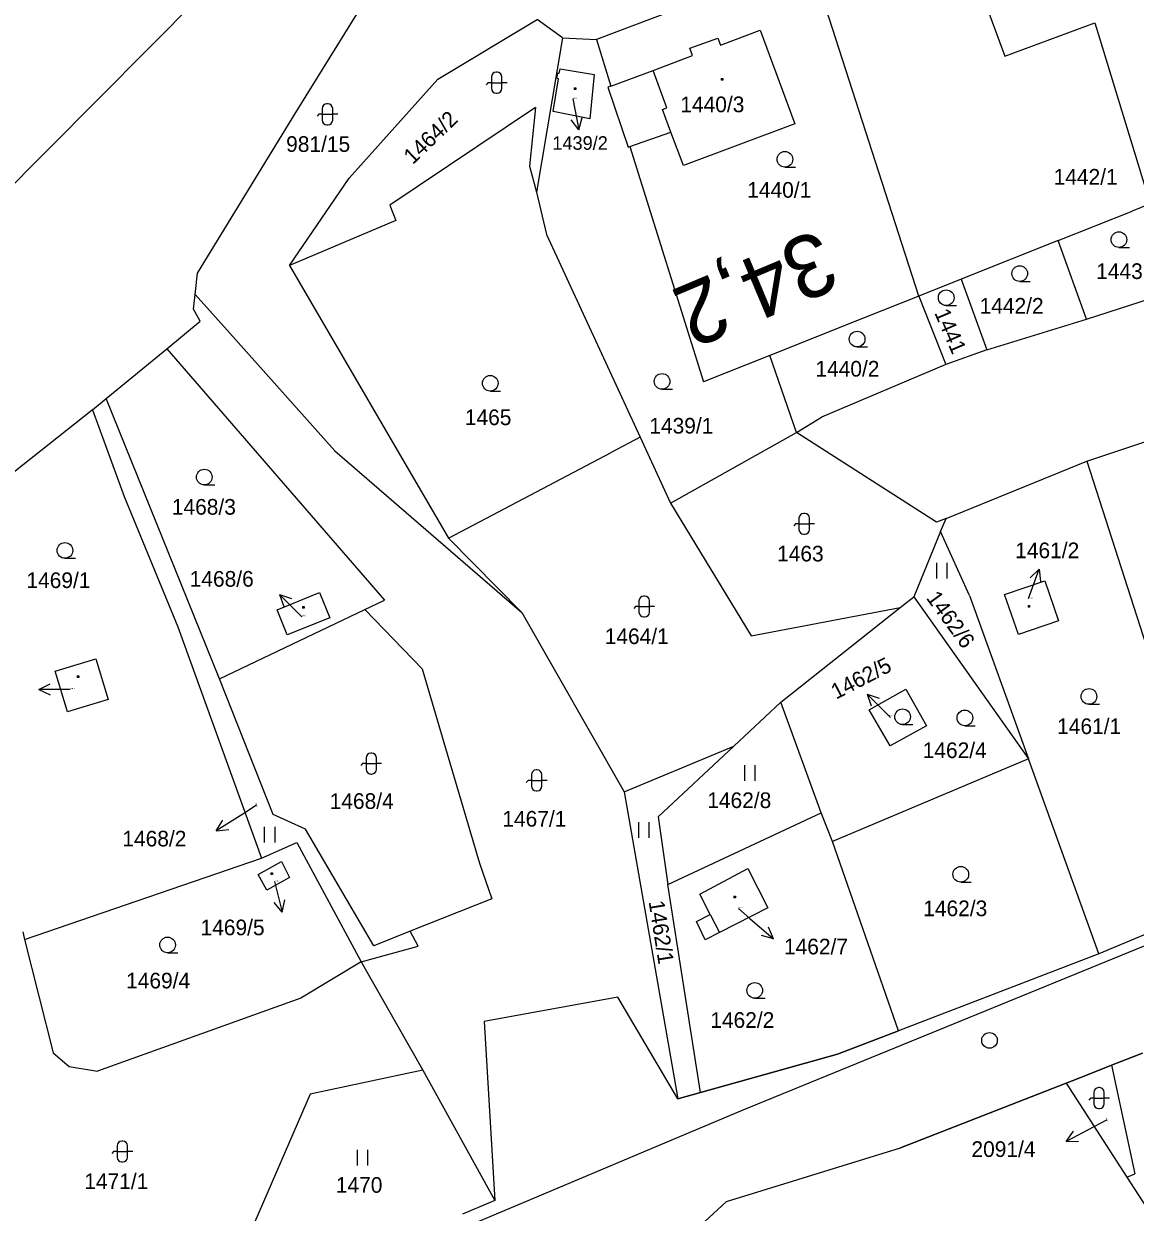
# Model space of a CAD drawing. Extents: x -805730 to -804640, y -1150889 to -1150366.
# Drawn here: x -805108.7 to -805002.2, y -1150618.3 to -1150504.4 of the extents above; entities that cross this region are included whole.
import ezdxf

# ---------------------------------------------------------------- set-up
doc = ezdxf.new("R2010")
doc.units = 0
for name, color, linetype in [('Default', 7, 'Continuous'), ('kilometráž - vrstava 7', 7, 'Continuous'), ('kn_celek - Cisla parcel pomocna', 7, 'Continuous'), ('kn_celek - Cisla pozemkovych parcel', 7, 'Continuous'), ('kn_celek - Cisla stavebnich parcel', 7, 'Continuous'), ('kn_celek - Hranice parcel', 7, 'Continuous'), ('kn_celek - Vnitrni kresby', 7, 'Continuous'), ('kn_celek - Znacky budov', 7, 'Continuous'), ('kn_celek - Znacky kultur', 7, 'Continuous'), ('plochy - SZDC', 7, 'Continuous'), ('PSR_C2_2_trasa_Vimperk - Kabelová trasa', 7, 'Continuous')]:
    doc.layers.add(name, color=color, linetype=linetype)

# ---------------------------------------------------------------- blocks, each defined once
blk = doc.blocks.new('316')
at = {"layer": 'Default'}
for p, q in [((-5, 15.5), (-5, 4.5)), ((0.5, 20), (-0.5, 20)), ((5, 4.5), (5, 15.5)), ((-8.3, 10), (-10, 8.1)), ((-5, 10), (-8.3, 10)), ((-5, 10), (5, 10)), ((-0.5, 0), (0.5, 0)), ((10, 10), (5, 10))]:
    blk.add_line(p, q, dxfattribs=at)
for centre, start, end in [((-0.5, 15.5), 90, 180), ((0.5, 15.5), 0, 90), ((-0.5, 4.5), 180, 270), ((0.5, 4.5), 270, 0)]:
    blk.add_arc(centre, 4.5, start, end, dxfattribs=at)
blk = doc.blocks.new('304')
at = {"layer": 'Default'}
blk.add_line((-0.1, 0), (9.9, 0), dxfattribs=at)
blk.add_circle((-0.1, 7.5), 7.5, dxfattribs=at)
blk = doc.blocks.new('306')
at = {"layer": 'Default'}
for p, q in [((-5.2, 0), (-5.2, 15)), ((4.8, 0), (4.8, 15))]:
    blk.add_line(p, q, dxfattribs=at)
blk = doc.blocks.new('402')
at = {"layer": 'Default'}
for p, q in [((-0.8, 0.8), (0.7, 0.8)), ((-0.8, 0.8), (-0.8, -0.7)), ((0.7, 0.8), (0.7, -0.7)), ((0.7, -0.7), (-0.8, -0.7))]:
    blk.add_line(p, q, dxfattribs=at)
blk = doc.blocks.new('Z61')
at = {"layer": 'Default'}
for p, q in [((0, 0), (30, 0)), ((30, 0), (19.2, 5.3)), ((30, 0), (19.2, -5.3))]:
    blk.add_line(p, q, dxfattribs=at)

msp = doc.modelspace()

# ---------------------------------------------------------------- linework, layer by layer
at = {"layer": 'kilometráž - vrstava 7'}
msp.add_circle((-805016.2, -1150601.85), 0.75, dxfattribs=at)
at = {"layer": 'kn_celek - Cisla parcel pomocna'}
for p, q in [((-805025.69, -1150570.9), (-805025.8, -1150570.79)), ((-805086.41, -1150579.31), (-805087.74, -1150580.16)), ((-805040.25, -1150589.23), (-805039.17, -1150590.16)), ((-805004.99, -1150609.51), (-805006.2, -1150610.14))]:
    msp.add_line(p, q, dxfattribs=at)
at = {"layer": 'kn_celek - Hranice parcel'}
for p, q in [((-805079.5, -1150489.41), (-805112.27, -1150522.42)), ((-805018.53, -1150497.21), (-805014.72, -1150507.54)), ((-805033.4, -1150498.22), (-805053.85, -1150505.95)), ((-805022.97, -1150530.54), (-805033.4, -1150498.22)), ((-805082.65, -1150512.94), (-805074.55, -1150499.86)), ((-805069.04, -1150509.76), (-805059.52, -1150504.03)), ((-805057.1, -1150505.8), (-805059.52, -1150504.03)), ((-805014.72, -1150507.54), (-805006.12, -1150504.36)), ((-805006.12, -1150504.36), (-805000.8, -1150521.71)), ((-805041.98, -1150506.5), (-805038.18, -1150505.06)), ((-805038.18, -1150505.06), (-805034.85, -1150514.03)), ((-805057.1, -1150505.8), (-805059.6, -1150520.58)), ((-805057.1, -1150505.8), (-805053.85, -1150505.95)), ((-805053.85, -1150505.95), (-805052.46, -1150510.42)), ((-805044.9, -1150506.79), (-805042.23, -1150505.81)), ((-805044.64, -1150507.48), (-805044.9, -1150506.79)), ((-805042.23, -1150505.81), (-805041.98, -1150506.5)), ((-805048.42, -1150508.92), (-805044.64, -1150507.48)), ((-805057.41, -1150509.19), (-805057.33, -1150508.76)), ((-805057.33, -1150508.76), (-805054.07, -1150509.3)), ((-805052.46, -1150510.42), (-805048.42, -1150508.92)), ((-805077.55, -1150519.25), (-805069.04, -1150509.76)), ((-805058, -1150512.84), (-805057.49, -1150509.72)), ((-805057.63, -1150509.69), (-805057.57, -1150509.17)), ((-805057.49, -1150509.72), (-805057.63, -1150509.69)), ((-805057.57, -1150509.17), (-805057.41, -1150509.19)), ((-805054.07, -1150509.3), (-805054.49, -1150513.55)), ((-805052.46, -1150510.42), (-805052.77, -1150510.53)), ((-805052.77, -1150510.53), (-805050.82, -1150516.26)), ((-805059.7, -1150512.48), (-805073.66, -1150521.82)), ((-805059.7, -1150512.48), (-805060.27, -1150518.1)), ((-805092.06, -1150528.34), (-805082.65, -1150512.94)), ((-805054.49, -1150513.55), (-805058, -1150512.84)), ((-805050.65, -1150516.2), (-805046.73, -1150514.83)), ((-805045.5, -1150518.02), (-805046.73, -1150514.83)), ((-805034.85, -1150514.03), (-805045.5, -1150518.02)), ((-805050.82, -1150516.26), (-805050.65, -1150516.2)), ((-805050.65, -1150516.2), (-805043.6, -1150538.76)), ((-805060.27, -1150518.1), (-805059.6, -1150520.58)), ((-805083.26, -1150527.62), (-805077.55, -1150519.25)), ((-805059.6, -1150520.58), (-805058.64, -1150524.62)), ((-805073.66, -1150521.82), (-805073.06, -1150523.3)), ((-805009.62, -1150525.22), (-805002.53, -1150522.4)), ((-805000.8, -1150521.71), (-805002.53, -1150522.4)), ((-805073.06, -1150523.3), (-805083.26, -1150527.62)), ((-805058.64, -1150524.62), (-805049.67, -1150544.06)), ((-805009.62, -1150525.22), (-805018.9, -1150528.92)), ((-805006.9, -1150532.75), (-805009.62, -1150525.22)), ((-805092.29, -1150530.39), (-805092.06, -1150528.34)), ((-805083.26, -1150527.62), (-805068.03, -1150553.72)), ((-805018.9, -1150528.92), (-805022.97, -1150530.54)), ((-805018.9, -1150528.92), (-805016.44, -1150535.7)), ((-805092.46, -1150531.79), (-805092.29, -1150530.39)), ((-805092.29, -1150530.39), (-805089.24, -1150533.8)), ((-805022.97, -1150530.54), (-805028.2, -1150532.62)), ((-805022.97, -1150530.54), (-805020.37, -1150537.08)), ((-805006.9, -1150532.75), (-804997.39, -1150529.68)), ((-805091.82, -1150532.95), (-805092.46, -1150531.79)), ((-805095, -1150535.6), (-805091.82, -1150532.95)), ((-805028.2, -1150532.62), (-805037.23, -1150536.22)), ((-805016.44, -1150535.7), (-805006.9, -1150532.75)), ((-805089.24, -1150533.8), (-805078.93, -1150545.36)), ((-805100.81, -1150540.35), (-805095, -1150535.6)), ((-805095, -1150535.6), (-805074.17, -1150559.68)), ((-805037.23, -1150536.22), (-805043.6, -1150538.76)), ((-805034.69, -1150543.61), (-805037.23, -1150536.22)), ((-805016.44, -1150535.7), (-805020.37, -1150537.08)), ((-805020.37, -1150537.08), (-805032.29, -1150542.13)), ((-805102.12, -1150541.42), (-805100.81, -1150540.35)), ((-805089.98, -1150567.2), (-805100.81, -1150540.35)), ((-805121.16, -1150556.44), (-805102.15, -1150541.44)), ((-805102.15, -1150541.44), (-805102.12, -1150541.42)), ((-805102.12, -1150541.42), (-805099.11, -1150549.73)), ((-805034.69, -1150543.61), (-805032.29, -1150542.13)), ((-805006.87, -1150546.34), (-804993.42, -1150541.84)), ((-805049.67, -1150544.06), (-805052.45, -1150545.52)), ((-805049.67, -1150544.06), (-805046.75, -1150550.37)), ((-805046.75, -1150550.37), (-805034.69, -1150543.61)), ((-805021.28, -1150552.21), (-805034.69, -1150543.61)), ((-805078.93, -1150545.36), (-805061, -1150560.85)), ((-805068.03, -1150553.72), (-805052.45, -1150545.52)), ((-805020.36, -1150551.84), (-805006.87, -1150546.34)), ((-805006.87, -1150546.34), (-804993.4, -1150588.37)), ((-805099.11, -1150549.73), (-805093.95, -1150562.24)), ((-805046.75, -1150550.37), (-805039.03, -1150563.1)), ((-805020.36, -1150551.84), (-805021.28, -1150552.21)), ((-805020.88, -1150553.1), (-805020.36, -1150551.84)), ((-805020.88, -1150553.1), (-805023.46, -1150559.34)), ((-805018.12, -1150559.23), (-805020.88, -1150553.1)), ((-805068.03, -1150553.72), (-805061, -1150560.85)), ((-805014.76, -1150559.13), (-805010.91, -1150557.83)), ((-805010.91, -1150557.83), (-805009.6, -1150561.66)), ((-805084.45, -1150560.6), (-805080.38, -1150558.93)), ((-805080.38, -1150558.93), (-805079.41, -1150561.35)), ((-805018.12, -1150559.23), (-805012.48, -1150574.86)), ((-805013.43, -1150562.97), (-805014.76, -1150559.13)), ((-805076.03, -1150560.57), (-805074.17, -1150559.68)), ((-805039.03, -1150563.1), (-805024.75, -1150560.36)), ((-805036.2, -1150569.44), (-805024.75, -1150560.36)), ((-805024.75, -1150560.36), (-805023.46, -1150559.34)), ((-805023.46, -1150559.34), (-805012.48, -1150574.86)), ((-805089.98, -1150567.2), (-805076.03, -1150560.57)), ((-805083.48, -1150563), (-805084.45, -1150560.6)), ((-805079.41, -1150561.35), (-805083.48, -1150563)), ((-805076.03, -1150560.57), (-805070.55, -1150566.25)), ((-805061, -1150560.85), (-805051.2, -1150578.03)), ((-805093.95, -1150562.24), (-805085.94, -1150584.38)), ((-805009.6, -1150561.66), (-805013.43, -1150562.97)), ((-805105.71, -1150566.46), (-805101.82, -1150565.29)), ((-805101.82, -1150565.29), (-805100.64, -1150569.18)), ((-805104.54, -1150570.36), (-805105.71, -1150566.46)), ((-805084.82, -1150580.22), (-805089.98, -1150567.2)), ((-805070.55, -1150566.25), (-805068.17, -1150574.39)), ((-805027.73, -1150570.18), (-805024.21, -1150568.19)), ((-805024.21, -1150568.19), (-805022.22, -1150571.72)), ((-805100.64, -1150569.18), (-805104.54, -1150570.36)), ((-805040.7, -1150573.65), (-805036.2, -1150569.44)), ((-805032.33, -1150580.05), (-805036.2, -1150569.44)), ((-805025.73, -1150573.63), (-805027.73, -1150570.18)), ((-805022.22, -1150571.72), (-805025.73, -1150573.63)), ((-805040.7, -1150573.65), (-805047.95, -1150580.43)), ((-805041.83, -1150574.14), (-805040.7, -1150573.65)), ((-805068.17, -1150574.39), (-805065.07, -1150584.87)), ((-805051.2, -1150578.03), (-805041.83, -1150574.14)), ((-805012.48, -1150574.86), (-805031.23, -1150582.81)), ((-805005.74, -1150593.57), (-805012.48, -1150574.86)), ((-805051.2, -1150578.03), (-805046.06, -1150607.46)), ((-805083.41, -1150580.85), (-805084.82, -1150580.22)), ((-805081.74, -1150581.6), (-805083.41, -1150580.85)), ((-805047.95, -1150580.43), (-805047.01, -1150586.93)), ((-805047.01, -1150586.93), (-805032.33, -1150580.05)), ((-805031.23, -1150582.81), (-805032.33, -1150580.05)), ((-805075.19, -1150592.79), (-805081.74, -1150581.6)), ((-805085.94, -1150584.38), (-805082.55, -1150582.89)), ((-805082.55, -1150582.89), (-805076.38, -1150594.32)), ((-805024.92, -1150600.92), (-805031.23, -1150582.81)), ((-805108.63, -1150592.17), (-805085.94, -1150584.38)), ((-805086.27, -1150585.97), (-805084.04, -1150584.71)), ((-805084.04, -1150584.71), (-805083.26, -1150586.25)), ((-805065.07, -1150584.87), (-805063.88, -1150588.3)), ((-805043.96, -1150587.84), (-805039.35, -1150585.37)), ((-805039.35, -1150585.37), (-805037.45, -1150589.16)), ((-805085.43, -1150587.47), (-805086.27, -1150585.97)), ((-805083.26, -1150586.25), (-805085.43, -1150587.47)), ((-805043.88, -1150606.84), (-805047.01, -1150586.93)), ((-805063.88, -1150588.3), (-805071.69, -1150591.4)), ((-805042.96, -1150589.8), (-805043.96, -1150587.84)), ((-804993.4, -1150588.37), (-805005.74, -1150593.57)), ((-805044.26, -1150590.47), (-805042.96, -1150589.8)), ((-805037.45, -1150589.16), (-805042.07, -1150591.52)), ((-805043.43, -1150592.22), (-805044.26, -1150590.47)), ((-805108.82, -1150591.44), (-805108.63, -1150592.17)), ((-805108.63, -1150592.17), (-805105.9, -1150603.05)), ((-805071.69, -1150591.4), (-805075.19, -1150592.79)), ((-805070.94, -1150592.82), (-805071.69, -1150591.4)), ((-805042.07, -1150591.52), (-805043.43, -1150592.22)), ((-805076.38, -1150594.32), (-805070.94, -1150592.82)), ((-805076.38, -1150594.32), (-805082.18, -1150597.79)), ((-805076.38, -1150594.32), (-805070.48, -1150604.71)), ((-805005.74, -1150593.57), (-805024.92, -1150600.92)), ((-805082.18, -1150597.79), (-805101.64, -1150604.8)), ((-805051.81, -1150597.72), (-805064.61, -1150600.03)), ((-805046.06, -1150607.46), (-805051.81, -1150597.72)), ((-805064.61, -1150600.03), (-805063.58, -1150617.18)), ((-805030.76, -1150603.16), (-805024.92, -1150600.92)), ((-805105.9, -1150603.05), (-805104.38, -1150604.34)), ((-805043.88, -1150606.84), (-805030.76, -1150603.16)), ((-805001.53, -1150603.08), (-805004.51, -1150604.24)), ((-805104.38, -1150604.34), (-805101.64, -1150604.8)), ((-805070.48, -1150604.71), (-805081.28, -1150606.99)), ((-805070.48, -1150604.71), (-805063.58, -1150617.18)), ((-805004.51, -1150604.24), (-805006.96, -1150605.2)), ((-805004.51, -1150604.24), (-805002.27, -1150614.63)), ((-805008.86, -1150605.94), (-805024.72, -1150612.14)), ((-805006.96, -1150605.2), (-805008.86, -1150605.94)), ((-805008.86, -1150605.94), (-805003.05, -1150614.96)), ((-805081.28, -1150606.99), (-805086.98, -1150620.2)), ((-805046.06, -1150607.46), (-805043.88, -1150606.84)), ((-805041.4, -1150617.28), (-805024.72, -1150612.14)), ((-805003.05, -1150614.96), (-805002.27, -1150614.63)), ((-805003.05, -1150614.96), (-804998.33, -1150622.28)), ((-805063.58, -1150617.18), (-805066.7, -1150618.51)), ((-805043.51, -1150619.25), (-805041.4, -1150617.28))]:
    msp.add_line(p, q, dxfattribs=at)
at = {"layer": 'kn_celek - Vnitrni kresby'}
for p, q in [((-805047.1, -1150512.5), (-805048.42, -1150508.92)), ((-805047.53, -1150512.66), (-805047.1, -1150512.5)), ((-805046.73, -1150514.83), (-805047.53, -1150512.66)), ((-805042.96, -1150589.8), (-805042.07, -1150591.52))]:
    msp.add_line(p, q, dxfattribs=at)
at = {"layer": 'plochy - SZDC'}
for p, q in [((-804993.4, -1150588.37), (-805005.74, -1150593.57)), ((-805005.74, -1150593.57), (-805024.92, -1150600.92)), ((-805051.81, -1150597.72), (-805064.61, -1150600.03)), ((-805046.06, -1150607.46), (-805051.81, -1150597.72)), ((-805064.61, -1150600.03), (-805063.58, -1150617.18)), ((-805024.92, -1150600.92), (-805030.76, -1150603.16)), ((-805030.76, -1150603.16), (-805043.88, -1150606.84)), ((-805004.51, -1150604.24), (-805001.53, -1150603.08)), ((-805006.96, -1150605.2), (-805004.51, -1150604.24)), ((-805024.72, -1150612.14), (-805008.86, -1150605.94)), ((-805008.86, -1150605.94), (-805006.96, -1150605.2)), ((-805043.88, -1150606.84), (-805046.06, -1150607.46)), ((-805041.4, -1150617.28), (-805024.72, -1150612.14)), ((-805063.58, -1150617.18), (-805066.7, -1150618.51)), ((-805043.51, -1150619.25), (-805041.4, -1150617.28))]:
    msp.add_line(p, q, dxfattribs=at)
at = {"layer": 'PSR_C2_2_trasa_Vimperk - Kabelová trasa'}
msp.add_lwpolyline([(-805122.45, -1150641.59), (-805112.53, -1150638.37), (-805102.25, -1150634.46), (-805084.03, -1150627.11), (-805075.4, -1150623.5), (-805060.17, -1150617.08), (-805047.9, -1150611.92), (-805039.79, -1150608.5), (-804989.01, -1150587.76)], dxfattribs=at)

# ---------------------------------------------------------------- block references
at = {"layer": 'kn_celek - Cisla parcel pomocna'}
for p, xscale, yscale, rotation in [((-805056.12, -1150511.65), 0.09999999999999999, 0.10000000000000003, -79.08884999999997), ((-805012.45, -1150559.52), 0.1, 0.10000000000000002, 70.56009000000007), ((-805082.08, -1150561.26), 0.1, 0.10000000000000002, 135), ((-805104.26, -1150568.22), 0.1, 0.10000000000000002, -179.99999999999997), ((-805025.8, -1150570.79), 0.1, 0.10000000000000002, 135), ((-805087.74, -1150580.16), 0.10000000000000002, 0.1, -147.49047), ((-805084.69, -1150586.64), 0.09999999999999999, 0.10000000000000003, -75.96378), ((-805039.17, -1150590.16), 0.1, 0.09999999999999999, -40.601249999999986), ((-805006.2, -1150610.14), 0.10000000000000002, 0.1, -152.55342)]:
    msp.add_blockref('Z61', p, dxfattribs=dict(at, xscale=xscale, yscale=yscale, rotation=rotation))
at = {"layer": 'kn_celek - Znacky budov', "xscale": 0.1, "yscale": 0.10000000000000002}
for p in [(-805041.83, -1150509.77), (-805055.91, -1150510.66), (-805081.93, -1150560.36), (-805012.43, -1150560.26), (-805103.52, -1150567), (-805084.97, -1150585.89), (-805040.6, -1150588.11)]:
    msp.add_blockref('402', p, dxfattribs=at)
at = {"layer": 'kn_celek - Znacky kultur', "xscale": 0.1, "yscale": 0.10000000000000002}
for name, p in [('316', (-805063.42, -1150511.09)), ('316', (-805079.62, -1150514.12)), ('304', (-805035.79, -1150518.18)), ('304', (-805003.79, -1150525.88)), ('304', (-805013.3, -1150529.13)), ('304', (-805020.34, -1150531.44)), ('304', (-805028.87, -1150535.41)), ('304', (-805064.02, -1150539.64)), ('304', (-805047.56, -1150539.46)), ('304', (-805091.41, -1150548.63)), ('316', (-805033.95, -1150553.36)), ('304', (-805104.76, -1150555.66)), ('306', (-805020.73, -1150557.59)), ('316', (-805049.28, -1150561.28)), ('304', (-805006.66, -1150569.65)), ('304', (-805024.52, -1150571.59)), ('304', (-805018.55, -1150571.7)), ('316', (-805075.43, -1150576.33)), ('316', (-805059.58, -1150577.94)), ('306', (-805039.13, -1150576.99)), ('306', (-805085.12, -1150582.9)), ('306', (-805049.27, -1150582.43)), ('304', (-805018.94, -1150586.69)), ('304', (-805094.93, -1150593.45)), ('304', (-805038.68, -1150597.81)), ('316', (-805005.7, -1150608.38)), ('316', (-805099.28, -1150613.5)), ('306', (-805076.22, -1150613.85))]:
    msp.add_blockref(name, p, dxfattribs=at)

# ---------------------------------------------------------------- texts
at = {"layer": 'kilometráž - vrstava 7'}
msp.add_text('34,2', height=6, rotation=202.7734, dxfattribs=at).set_placement((-805032.54, -1150524.04))
at = {"layer": 'kn_celek - Cisla parcel pomocna'}
for s, height, p in [('1439/2', 1.3, (-805058.08, -1150516.52)), ('1461/2', 1.5, (-805013.74, -1150555.65)), ('1468/6', 1.5, (-805092.82, -1150558.38)), ('1468/2', 1.5, (-805099.27, -1150583.27)), ('1469/5', 1.5, (-805091.78, -1150591.78)), ('1462/7', 1.5, (-805035.89, -1150593.61)), ('2091/4', 1.5, (-805017.93, -1150613.02))]:
    msp.add_text(s, height=height, dxfattribs=at).set_placement(p)
msp.add_text('1462/5', height=1.5, rotation=27.3017, dxfattribs=at).set_placement((-805030.89, -1150569.21))
at = {"layer": 'kn_celek - Cisla pozemkovych parcel'}
for s, height, rotation, p in [('1464/2', 1.5, 43.847, (-805071.45, -1150517.99)), ('1441', 1.5, 293.4, (-805021.51, -1150532.13)), ('1462/6', 1.5, 306, (-805022.32, -1150559.47)), ('1468/2', 0.1, 289.8, (-805086.55, -1150579.08)), ('1462/1', 1.5, 279, (-805048.86, -1150588.56)), ('2091/4', 0.1, 293.3105, (-805005.07, -1150609.25))]:
    msp.add_text(s, height=height, rotation=rotation, dxfattribs=at).set_placement(p)
for s, height, p in [('981/15', 1.5, (-805083.58, -1150516.72)), ('1442/1', 1.5, (-805010.06, -1150519.86)), ('1440/1', 1.5, (-805039.41, -1150521.11)), ('1443', 1.5, (-805005.98, -1150528.9)), ('1442/2', 1.5, (-805017.15, -1150532.22)), ('1440/2', 1.5, (-805032.88, -1150538.25)), ('1465', 1.5, (-805066.46, -1150542.9)), ('1439/1', 1.5, (-805048.79, -1150543.71)), ('1468/3', 1.5, (-805094.53, -1150551.48)), ('1463', 1.5, (-805036.55, -1150555.96)), ('1469/1', 1.5, (-805108.46, -1150558.51)), ('1464/1', 1.5, (-805053.06, -1150563.88)), ('1462/5', 0.1, (-805025.91, -1150570.76)), ('1461/1', 1.5, (-805009.72, -1150572.5)), ('1462/4', 1.5, (-805022.6, -1150574.8)), ('1468/4', 1.5, (-805079.41, -1150579.67)), ('1462/8', 1.5, (-805043.24, -1150579.59)), ('1467/1', 1.5, (-805062.87, -1150581.37)), ('1462/3', 1.5, (-805022.55, -1150589.95)), ('1469/4', 1.5, (-805098.91, -1150596.87)), ('1462/2', 1.5, (-805042.95, -1150600.65)), ('1471/1', 1.5, (-805102.92, -1150616.1)), ('1470', 1.5, (-805078.82, -1150616.45))]:
    msp.add_text(s, height=height, dxfattribs=at).set_placement(p)
at = {"layer": 'kn_celek - Cisla stavebnich parcel'}
for s, height, p in [('1440/3', 1.5, (-805045.82, -1150512.92)), ('1439/2', 0.1, (-805056.12, -1150511.62)), ('1461/2', 0.1, (-805012.45, -1150559.49)), ('1468/6', 0.1, (-805082.08, -1150561.23)), ('1469/2', 0.1, (-805104.26, -1150568.19)), ('1469/5', 0.1, (-805084.69, -1150586.61)), ('1462/7', 0.1, (-805040.25, -1150589.2))]:
    msp.add_text(s, height=height, dxfattribs=at).set_placement(p)

doc.saveas('drawing.dxf')
